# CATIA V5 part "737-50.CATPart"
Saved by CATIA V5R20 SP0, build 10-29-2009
Part number: 737-50
Definition: NONE
Nomenclature: 737-50
Source: Unknown
Description: 737-50
Bounding box of the stored display mesh (mm): x -52 to 38, y -51.97 to 51.97, z -60 to 42
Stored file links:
  C:\Users\Utente\Desktop\IO LAVORO\3D X SITO CF\X SITO\737\737-50.CATPart
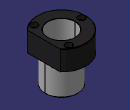
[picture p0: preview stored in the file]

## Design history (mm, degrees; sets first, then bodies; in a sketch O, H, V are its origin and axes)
Body1 "737-50" (main body)
  Solid1: solid without history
